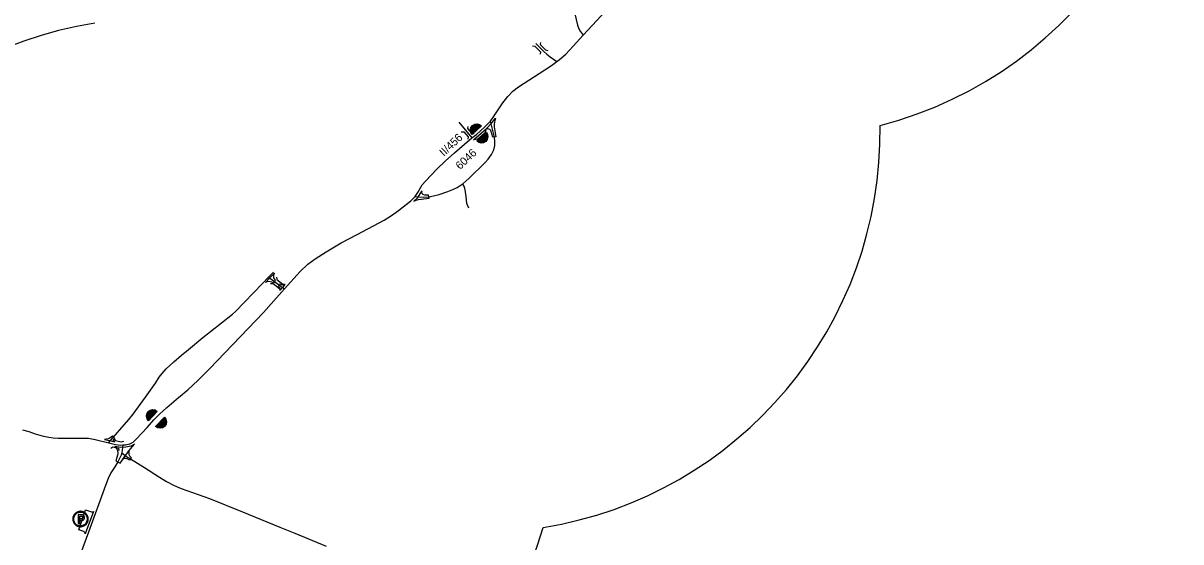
# Model space of a CAD drawing. Extents: x -546703 to -534152, y -1046534 to -1035676.
# Drawn here: x -543551 to -542104, y -1040697 to -1040049 of the extents above; entities that cross this region are included whole.
import ezdxf

# ---------------------------------------------------------------- set-up
doc = ezdxf.new("R2010")
doc.units = 0
for name, color, linetype in [('Vrstva 11', 7, 'Continuous'), ('Vrstva 19', 7, 'Continuous'), ('Vrstva 22', 7, 'Continuous'), ('Vrstva 23', 7, 'Continuous'), ('Vrstva 26', 7, 'Continuous'), ('Vrstva 3', 7, 'Continuous'), ('Vrstva 4', 7, 'Continuous'), ('Vrstva 46', 7, 'Continuous'), ('Vrstva 7', 7, 'Continuous'), ('Vrstva 8', 7, 'Continuous')]:
    doc.layers.add(name, color=color, linetype=linetype)

msp = doc.modelspace()

# ---------------------------------------------------------------- linework, layer by layer
at = {"layer": 'Vrstva 11'}
msp.add_line((-543006.5, -1040172.6), (-542990.1, -1040192.3), dxfattribs=at)
at = {"layer": 'Vrstva 19'}
msp.add_lwpolyline([(-543481.2, -1040681.7), (-543479.2, -1040675.6), (-543472.8, -1040656.7), (-543465.6, -1040659.1), (-543465.6, -1040659.1), (-543464.6, -1040659.2), (-543463.7, -1040659), (-543463, -1040658.6), (-543472, -1040683.4), (-543473.2, -1040686.6), (-543473.4, -1040685.2), (-543474, -1040684.4), (-543474.9, -1040683.8)], close=True, dxfattribs=at)
at = {"layer": 'Vrstva 22'}
msp.add_lwpolyline([(-543551.7, -1040556.7), (-543543.7, -1040559), (-543535.7, -1040561.7), (-543527.1, -1040564.4), (-543518.9, -1040566.1), (-543513.5, -1040566.6), (-543507, -1040567.2), (-543497.8, -1040567.2), (-543480.6, -1040567.3), (-543473.8, -1040567.3), (-543469.4, -1040567.4), (-543461, -1040568.9), (-543443.8, -1040573.1), (-543435.5, -1040574.9), (-543428.8, -1040575.8), (-543426.3, -1040575.7), (-543423.1, -1040575.5), (-543417.6, -1040574.1), (-543413.6, -1040572.1), (-543409.5, -1040568.4), (-543402.5, -1040560.9), (-543396, -1040553.7), (-543387.6, -1040544.5), (-543380.3, -1040537.1), (-543371.5, -1040528.8), (-543356.6, -1040516.5), (-543345.2, -1040507), (-543332.2, -1040494.9), (-543317.4, -1040480.4), (-543279.6, -1040440.7), (-543250.4, -1040410.4), (-543237.5, -1040395.7), (-543224.3, -1040380.6), (-543204.6, -1040359), (-543195.1, -1040350.1), (-543186.1, -1040343.3), (-543172.1, -1040334.6), (-543153.4, -1040323.5), (-543133.6, -1040312.8), (-543099.7, -1040295.1), (-543090.5, -1040289.3), (-543081.7, -1040282.9), (-543066.5, -1040270.7), (-543061, -1040265.5), (-543057.7, -1040260.7), (-543052.1, -1040251), (-543048.3, -1040246.3), (-543033.5, -1040231.1), (-543023.4, -1040221.3), (-543011.8, -1040210.8), (-542999.6, -1040200.1), (-542990.1, -1040192.3), (-542984.6, -1040187.9), (-542974.5, -1040179), (-542967, -1040171.3), (-542963, -1040166.1), (-542951.6, -1040148.7), (-542945.3, -1040140.6), (-542938.9, -1040133.9), (-542931.8, -1040128.4), (-542906.1, -1040112.1), (-542890.6, -1040101.9), (-542884.1, -1040096.9), (-542880.7, -1040094.4), (-542872.9, -1040087.6), (-542863.8, -1040077.9), (-542851, -1040064.2), (-542811.8, -1040021.9)], dxfattribs=at)
at = {"layer": 'Vrstva 23'}
for points in [[(-542989.4, -1040176.7), (-542986.7, -1040175.1), (-542983.6, -1040174.7), (-542980.5, -1040175.4), (-542978, -1040177.3), (-542990, -1040188.2), (-542991.7, -1040185.5), (-542992.1, -1040182.3), (-542991.3, -1040179.3)], [(-542989, -1040177.2), (-542986.5, -1040175.7), (-542983.6, -1040175.3), (-542980.8, -1040176), (-542979, -1040177.4), (-542989.9, -1040187.2), (-542991.1, -1040185.2), (-542991.5, -1040182.4), (-542990.8, -1040179.5)], [(-542988.6, -1040177.6), (-542986.3, -1040176.3), (-542983.7, -1040175.9), (-542981.1, -1040176.5), (-542979.9, -1040177.4), (-542989.8, -1040186.3), (-542990.5, -1040185), (-542990.9, -1040182.4), (-542990.2, -1040179.8)], [(-542988.2, -1040178.1), (-542986.1, -1040176.8), (-542983.7, -1040176.5), (-542981.3, -1040177.1), (-542980.8, -1040177.4), (-542989.6, -1040185.4), (-542989.9, -1040184.8), (-542990.3, -1040182.4), (-542989.7, -1040180)], [(-542987.8, -1040178.5), (-542985.9, -1040177.4), (-542983.7, -1040177.1), (-542981.9, -1040177.6), (-542989.4, -1040184.4), (-542989.7, -1040182.4), (-542989.1, -1040180.3)], [(-542987.4, -1040179), (-542985.7, -1040178), (-542983.8, -1040177.7), (-542983.1, -1040177.9), (-542989, -1040183.2), (-542989.1, -1040182.5), (-542988.6, -1040180.6)], [(-542987, -1040179.5), (-542985.5, -1040178.6), (-542984.6, -1040178.4), (-542988.2, -1040181.7), (-542988, -1040180.8)], [(-542972.8, -1040196.7), (-542975.5, -1040198.3), (-542978.6, -1040198.8), (-542981.7, -1040198), (-542984.2, -1040196.1), (-542972.1, -1040185.3), (-542970.5, -1040188), (-542970.1, -1040191.1), (-542970.9, -1040194.2)], [(-542973.2, -1040196.2), (-542975.7, -1040197.7), (-542978.6, -1040198.1), (-542981.4, -1040197.4), (-542983.2, -1040196), (-542972.3, -1040186.2), (-542971.1, -1040188.2), (-542970.7, -1040191.1), (-542971.4, -1040193.9)], [(-542973.6, -1040195.8), (-542975.9, -1040197.2), (-542978.5, -1040197.5), (-542981.1, -1040196.9), (-542982.3, -1040196), (-542972.4, -1040187.1), (-542971.7, -1040188.4), (-542971.3, -1040191.1), (-542972, -1040193.6)], [(-542974, -1040195.3), (-542976.1, -1040196.6), (-542978.5, -1040196.9), (-542980.9, -1040196.3), (-542981.4, -1040195.9), (-542972.5, -1040188.1), (-542972.2, -1040188.6), (-542971.9, -1040191), (-542972.5, -1040193.4)], [(-542974.4, -1040194.9), (-542976.3, -1040196), (-542978.5, -1040196.3), (-542980.3, -1040195.8), (-542972.8, -1040189.1), (-542972.5, -1040191), (-542973.1, -1040193.1)], [(-542974.8, -1040194.4), (-542976.5, -1040195.4), (-542978.4, -1040195.7), (-542979.1, -1040195.5), (-542973.2, -1040190.3), (-542973.1, -1040190.9), (-542973.6, -1040192.9)], [(-542975.2, -1040194), (-542976.7, -1040194.8), (-542977.6, -1040195), (-542973.9, -1040191.7), (-542974.2, -1040192.6)], [(-543394.7, -1040534.1), (-543392.1, -1040532.2), (-543389.1, -1040531.5), (-543385.9, -1040532), (-543383.2, -1040533.7), (-543394.2, -1040545.5), (-543396.1, -1040543), (-543396.8, -1040539.9), (-543396.3, -1040536.8)], [(-543394.2, -1040534.5), (-543391.9, -1040532.8), (-543389, -1040532.1), (-543386.1, -1040532.6), (-543384.2, -1040533.8), (-543394.2, -1040544.6), (-543395.5, -1040542.7), (-543396.2, -1040539.9), (-543395.8, -1040537)], [(-543393.8, -1040534.9), (-543391.6, -1040533.3), (-543389, -1040532.7), (-543386.4, -1040533.1), (-543385.1, -1040533.9), (-543394.1, -1040543.7), (-543395, -1040542.5), (-543395.6, -1040539.9), (-543395.2, -1040537.2)], [(-543393.3, -1040535.3), (-543391.4, -1040533.9), (-543389, -1040533.3), (-543386.6, -1040533.7), (-543386, -1040534), (-543394.1, -1040542.7), (-543394.4, -1040542.2), (-543395, -1040539.8), (-543394.6, -1040537.4)], [(-543392.9, -1040535.8), (-543391.1, -1040534.5), (-543389, -1040533.9), (-543387.1, -1040534.3), (-543393.9, -1040541.7), (-543394.4, -1040539.8), (-543394, -1040537.6)], [(-543392.4, -1040536.2), (-543390.8, -1040535), (-543388.9, -1040534.6), (-543388.3, -1040534.7), (-543393.6, -1040540.5), (-543393.8, -1040539.8), (-543393.5, -1040537.8)], [(-543392, -1040536.6), (-543390.6, -1040535.6), (-543389.7, -1040535.4), (-543393, -1040538.9), (-543392.9, -1040538.1)], [(-543373.9, -1040552.3), (-543376.5, -1040554.2), (-543379.6, -1040554.9), (-543382.7, -1040554.3), (-543385.3, -1040552.7), (-543374.2, -1040540.9), (-543372.4, -1040543.5), (-543371.7, -1040546.6), (-543372.2, -1040549.7)], [(-543374.3, -1040551.9), (-543376.7, -1040553.6), (-543379.6, -1040554.3), (-543382.4, -1040553.8), (-543384.4, -1040552.5), (-543374.3, -1040541.8), (-543372.9, -1040543.7), (-543372.3, -1040546.6), (-543372.8, -1040549.5)], [(-543374.8, -1040551.5), (-543377, -1040553.1), (-543379.6, -1040553.7), (-543382.2, -1040553.2), (-543383.5, -1040552.4), (-543374.3, -1040542.8), (-543373.5, -1040544), (-543372.9, -1040546.6), (-543373.4, -1040549.2)], [(-543375.2, -1040551.1), (-543377.2, -1040552.5), (-543379.6, -1040553), (-543382, -1040552.6), (-543382.5, -1040552.3), (-543374.4, -1040543.7), (-543374.1, -1040544.2), (-543373.5, -1040546.6), (-543373.9, -1040549)], [(-543375.7, -1040550.7), (-543377.5, -1040551.9), (-543379.6, -1040552.4), (-543381.5, -1040552.1), (-543374.5, -1040544.8), (-543374.1, -1040546.6), (-543374.5, -1040548.8)], [(-543376.1, -1040550.2), (-543377.7, -1040551.4), (-543379.6, -1040551.8), (-543380.3, -1040551.7), (-543374.9, -1040546), (-543374.7, -1040546.6), (-543375.1, -1040548.6)], [(-543376.6, -1040549.8), (-543378, -1040550.8), (-543378.8, -1040551), (-543375.5, -1040547.5), (-543375.6, -1040548.4)]]:
    msp.add_lwpolyline(points, close=True, dxfattribs=at)
at = {"layer": 'Vrstva 26'}
for centre, start, end in [((-542604.4, -1039692.4), 284.3744, 180.9424), ((-543382.4, -1040542.8), 99.089, 344.2283), ((-542980.2, -1040185), 279.089, 0.9424)]:
    msp.add_arc(centre, 500, start, end, dxfattribs=at)
at = {"layer": 'Vrstva 3'}
msp.add_lwpolyline([(-543551.7, -1040556.7), (-543543.7, -1040559), (-543535.7, -1040561.7), (-543527.1, -1040564.4), (-543518.9, -1040566.1), (-543513.5, -1040566.6), (-543507, -1040567.2), (-543497.8, -1040567.2), (-543480.6, -1040567.3), (-543473.8, -1040567.3), (-543469.4, -1040567.4), (-543461, -1040568.9), (-543443.8, -1040573.1), (-543435.5, -1040574.9), (-543428.8, -1040575.8), (-543426.3, -1040575.7), (-543423.1, -1040575.5), (-543417.6, -1040574.1), (-543413.6, -1040572.1), (-543409.5, -1040568.4), (-543402.5, -1040560.9), (-543396, -1040553.7), (-543387.6, -1040544.5), (-543380.3, -1040537.1), (-543371.5, -1040528.8), (-543356.6, -1040516.5), (-543345.2, -1040507), (-543332.2, -1040494.9), (-543317.4, -1040480.4), (-543279.6, -1040440.7), (-543250.4, -1040410.4), (-543237.5, -1040395.7), (-543224.3, -1040380.6), (-543204.6, -1040359), (-543195.1, -1040350.1), (-543186.1, -1040343.3), (-543172.1, -1040334.6), (-543153.4, -1040323.5), (-543133.6, -1040312.8), (-543099.7, -1040295.1), (-543090.5, -1040289.3), (-543081.7, -1040282.9), (-543066.5, -1040270.7), (-543061, -1040265.5), (-543057.7, -1040260.7), (-543052.1, -1040251), (-543048.3, -1040246.3), (-543033.5, -1040231.1), (-543023.4, -1040221.3), (-543011.8, -1040210.8), (-542999.6, -1040200.1), (-542990.1, -1040192.3), (-542984.6, -1040187.9), (-542974.5, -1040179), (-542967, -1040171.3), (-542963, -1040166.1), (-542951.6, -1040148.7), (-542945.3, -1040140.6), (-542938.9, -1040133.9), (-542931.8, -1040128.4), (-542906.1, -1040112.1), (-542890.6, -1040101.9), (-542884.1, -1040096.9), (-542880.7, -1040094.4), (-542872.9, -1040087.6), (-542863.8, -1040077.9), (-542851, -1040064.2), (-542811.8, -1040021.9)], dxfattribs=at)
msp.add_lwpolyline([(-542972.3, -1040181.1), (-542973.8, -1040186.4), (-542982.8, -1040194), (-542988.2, -1040194.6)], close=True, dxfattribs=at)
at = {"layer": 'Vrstva 4'}
msp.add_lwpolyline([(-543426.3, -1040575.7), (-543427.7, -1040585.7), (-543428.4, -1040588.5), (-543432.4, -1040596.9), (-543436.2, -1040602.8), (-543441.2, -1040610.5), (-543444.8, -1040617.5), (-543448.1, -1040626.1), (-543469.2, -1040684.5), (-543479.2, -1040711.6)], dxfattribs=at)
msp.add_lwpolyline([(-543429.7, -1040598.3), (-543420.6, -1040585.4), (-543416.8, -1040580.5), (-543411.9, -1040574.6), (-543416.5, -1040577), (-543422.7, -1040578.5), (-543428.9, -1040578.9), (-543436.2, -1040577.8), (-543433.6, -1040580.5), (-543432.8, -1040582.7), (-543432.6, -1040586.2), (-543432.8, -1040588.6), (-543433.6, -1040591.4), (-543435, -1040595.4)], close=True, dxfattribs=at)
at = {"layer": 'Vrstva 46'}
for points in [[(-543479.2, -1040658.5), (-543480, -1040658.5), (-543481.2, -1040658.7), (-543482.4, -1040659.1), (-543483.5, -1040659.5), (-543484.5, -1040660.1), (-543485.5, -1040660.9), (-543486.4, -1040661.7), (-543487.1, -1040662.7), (-543487.7, -1040663.7), (-543488.2, -1040664.8), (-543488.6, -1040666), (-543488.8, -1040667.2), (-543488.8, -1040668.4), (-543488.7, -1040669.6), (-543488.4, -1040670.8), (-543488, -1040672), (-543487.5, -1040673), (-543486.8, -1040674), (-543486, -1040674.9), (-543485.1, -1040675.7), (-543484, -1040676.4), (-543483, -1040677), (-543481.8, -1040677.4), (-543480.6, -1040677.6), (-543479.4, -1040677.7), (-543478.2, -1040677.7), (-543477, -1040677.5), (-543475.8, -1040677.1), (-543474.7, -1040676.6), (-543473.7, -1040676), (-543472.7, -1040675.2), (-543471.9, -1040674.4), (-543471.2, -1040673.4), (-543470.6, -1040672.3), (-543470.1, -1040671.2), (-543469.8, -1040670), (-543469.6, -1040668.8), (-543469.6, -1040667.6), (-543469.8, -1040666.4), (-543470, -1040665.2), (-543470.5, -1040664.1), (-543471.1, -1040663), (-543471.8, -1040662), (-543472.6, -1040661.2), (-543473.5, -1040660.4), (-543474.5, -1040659.7), (-543475.6, -1040659.2), (-543476.8, -1040658.8), (-543478, -1040658.6), (-543479.2, -1040658.5)], [(-543470.6, -1040668.1), (-543470.6, -1040667), (-543470.8, -1040666), (-543471.2, -1040664.9), (-543471.6, -1040663.9), (-543472.2, -1040663), (-543472.9, -1040662.2), (-543473.7, -1040661.4), (-543474.6, -1040660.8), (-543475.6, -1040660.3), (-543476.6, -1040659.9), (-543477.7, -1040659.6), (-543478.7, -1040659.5), (-543479.8, -1040659.5), (-543480.9, -1040659.6), (-543482, -1040659.9), (-543483, -1040660.3), (-543483.9, -1040660.9), (-543484.8, -1040661.5), (-543485.6, -1040662.3), (-543486.3, -1040663.2), (-543486.9, -1040664.1), (-543487.3, -1040665.1), (-543487.6, -1040666.1), (-543487.8, -1040667.2), (-543487.8, -1040668.3), (-543487.8, -1040669.4), (-543487.5, -1040670.5), (-543487.2, -1040671.5), (-543486.7, -1040672.5), (-543486.1, -1040673.4), (-543485.3, -1040674.2), (-543484.5, -1040674.9), (-543483.6, -1040675.5), (-543482.7, -1040676), (-543481.6, -1040676.4), (-543480.6, -1040676.7), (-543479.5, -1040676.8), (-543478.4, -1040676.7), (-543477.3, -1040676.6), (-543476.3, -1040676.2), (-543475.3, -1040675.8), (-543474.3, -1040675.3), (-543473.5, -1040674.6), (-543472.7, -1040673.8), (-543472, -1040672.9), (-543471.5, -1040672), (-543471, -1040671), (-543470.7, -1040669.9), (-543470.6, -1040668.8), (-543470.6, -1040668.1)], [(-543479.2, -1040659.5), (-543478.5, -1040659.5), (-543477.4, -1040659.7), (-543476.3, -1040660), (-543475.3, -1040660.4), (-543474.4, -1040660.9), (-543473.5, -1040661.6), (-543472.8, -1040662.4), (-543472.1, -1040663.2), (-543471.5, -1040664.2), (-543471.1, -1040665.2), (-543470.8, -1040666.2), (-543470.6, -1040667.3), (-543470.6, -1040668.4), (-543470.7, -1040669.5), (-543470.9, -1040670.5), (-543471.3, -1040671.6), (-543471.8, -1040672.5), (-543472.4, -1040673.4), (-543473.1, -1040674.3), (-543473.9, -1040675), (-543474.9, -1040675.6), (-543475.8, -1040676.1), (-543476.9, -1040676.4), (-543477.9, -1040676.7), (-543479, -1040676.8), (-543480.1, -1040676.7), (-543481.2, -1040676.5), (-543482.2, -1040676.2), (-543483.2, -1040675.8), (-543484.2, -1040675.2), (-543485, -1040674.5), (-543485.8, -1040673.7), (-543486.4, -1040672.9), (-543487, -1040671.9), (-543487.4, -1040670.9), (-543487.7, -1040669.8), (-543487.8, -1040668.8), (-543487.8, -1040667.7), (-543487.7, -1040666.6), (-543487.5, -1040665.5), (-543487.1, -1040664.5), (-543486.5, -1040663.5), (-543485.9, -1040662.7), (-543485.2, -1040661.9), (-543484.3, -1040661.1), (-543483.4, -1040660.6), (-543482.4, -1040660.1), (-543481.4, -1040659.8), (-543480.3, -1040659.5), (-543479.2, -1040659.5)], [(-543477.6, -1040662.9), (-543482.3, -1040662.9), (-543482.3, -1040673.8), (-543480, -1040673.8), (-543480, -1040668.1)], [(-543480, -1040668.1), (-543480, -1040664.7)], [(-543480, -1040664.7), (-543478.1, -1040664.7)], [(-543478.1, -1040668.1), (-543480, -1040668.1)], [(-543480, -1040668.1), (-543480, -1040669.9)], [(-543480, -1040669.9), (-543477.6, -1040669.9)], [(-543479.2, -1040658.5), (-543479.2, -1040659.5)], [(-543479.2, -1040659.5), (-543479.2, -1040658.5)], [(-543478.1, -1040664.7), (-543478.1, -1040664.7), (-543478, -1040664.7), (-543477.5, -1040664.8), (-543477.4, -1040664.9), (-543477.2, -1040665), (-543477, -1040665.1), (-543476.9, -1040665.2), (-543476.7, -1040665.4), (-543476.5, -1040665.7), (-543476.4, -1040665.9), (-543476.3, -1040666.3), (-543476.3, -1040666.5), (-543476.4, -1040666.9), (-543476.5, -1040667.1), (-543476.7, -1040667.4), (-543476.8, -1040667.5), (-543476.9, -1040667.6), (-543477.2, -1040667.8), (-543477.4, -1040667.9), (-543477.6, -1040668), (-543478, -1040668.1), (-543478.1, -1040668.1)], [(-543477.6, -1040669.9), (-543477.1, -1040669.8), (-543476.8, -1040669.8), (-543476.5, -1040669.7), (-543476.3, -1040669.6), (-543476.1, -1040669.5), (-543475.9, -1040669.4), (-543475.7, -1040669.2), (-543475.4, -1040669.1), (-543475.2, -1040668.9), (-543475.1, -1040668.7), (-543474.9, -1040668.6), (-543474.7, -1040668.3), (-543474.6, -1040668.1), (-543474.5, -1040667.9), (-543474.4, -1040667.7), (-543474.3, -1040667.5), (-543474.2, -1040667.2), (-543474.1, -1040666.8), (-543474.1, -1040666.5), (-543474.1, -1040666.2), (-543474.2, -1040665.8), (-543474.2, -1040665.7), (-543474.3, -1040665.4), (-543474.4, -1040665.2), (-543474.6, -1040664.8), (-543474.7, -1040664.6), (-543474.9, -1040664.3), (-543475.1, -1040664.1), (-543475.2, -1040664), (-543475.4, -1040663.8), (-543475.7, -1040663.6), (-543475.9, -1040663.5), (-543476.1, -1040663.4), (-543476.3, -1040663.3), (-543476.5, -1040663.2), (-543476.7, -1040663.1), (-543477.1, -1040663), (-543477.6, -1040662.9)]]:
    msp.add_lwpolyline(points, dxfattribs=at)
at = {"layer": 'Vrstva 7'}
msp.add_line((-543244.2, -1040366.4), (-543224.3, -1040380.6), dxfattribs=at)
for points in [[(-542877.6, -1040030.5), (-542869.3, -1040028.9), (-542867.2, -1040029), (-542864.5, -1040030.1), (-542863, -1040032), (-542858.3, -1040051.6), (-542856.7, -1040056), (-542855.1, -1040059), (-542851, -1040064.2)], [(-542910.4, -1040074.4), (-542900.3, -1040084.4), (-542896.6, -1040088), (-542892.2, -1040091.1), (-542884.1, -1040096.9)], [(-543061, -1040265.5), (-543050.5, -1040266.5), (-543044, -1040265.8), (-543038.3, -1040264.6), (-543031.2, -1040262.8), (-543020.2, -1040259.1), (-543013.8, -1040256.8), (-543008.4, -1040254.3), (-543001.1, -1040249.4), (-542994.1, -1040243.2), (-542973.4, -1040223.2), (-542969.8, -1040218.8), (-542965.5, -1040213), (-542962.6, -1040207.4), (-542961.6, -1040201.9), (-542961.5, -1040196.7), (-542962.1, -1040191.3), (-542967, -1040171.3)], [(-542994.1, -1040280), (-542996.3, -1040274.3), (-542997.4, -1040265.5), (-542998.6, -1040257.2), (-542999.6, -1040253.4), (-543001.6, -1040249.9)], [(-543444.4, -1040572.9), (-543418.8, -1040544.1), (-543413.3, -1040537.3), (-543398.1, -1040516.2), (-543385.4, -1040498.4), (-543381, -1040491.1), (-543377.1, -1040486.4), (-543372, -1040480.8), (-543362.4, -1040471.7), (-543353.1, -1040463.4), (-543344.1, -1040456.4), (-543326.3, -1040441.6), (-543316.8, -1040433.9), (-543289.4, -1040412.4), (-543285.4, -1040408.9), (-543251.6, -1040374), (-543244.2, -1040366.4), (-543241.8, -1040363.8), (-543238.1, -1040359.8)], [(-543427.7, -1040585.7), (-543421.8, -1040590.1), (-543416.9, -1040593.1), (-543399.1, -1040603.9), (-543380.4, -1040615.8), (-543371.8, -1040621.2), (-543362.3, -1040626.2), (-543353.4, -1040629.9), (-543317.9, -1040642.5), (-543276.9, -1040659.1), (-543230.2, -1040678.3), (-543211.3, -1040685.9), (-543172.1, -1040702.1)]]:
    msp.add_lwpolyline(points, dxfattribs=at)
for points in [[(-542964.1, -1040191.6), (-542966.6, -1040183.3), (-542967.9, -1040181.7), (-542970.1, -1040180.9), (-542972.3, -1040181.1), (-542964.7, -1040173.2), (-542960.5, -1040167.8), (-542961.9, -1040172.8), (-542962.2, -1040175.3), (-542962.4, -1040178.7), (-542960.1, -1040190.9)], [(-543044.3, -1040263.8), (-543048.8, -1040263.7), (-543051.2, -1040262.8), (-543052.1, -1040261.9), (-543052.9, -1040260.2), (-543052.9, -1040258.4), (-543055.1, -1040262.3), (-543058.7, -1040267.5), (-543062.9, -1040271.4), (-543059.9, -1040270), (-543056.7, -1040269.2), (-543053.1, -1040268.8), (-543050.4, -1040268.5), (-543043.7, -1040267.7)], [(-543236.8, -1040361), (-543238, -1040363.5), (-543238.2, -1040365.4), (-543238, -1040366.9), (-543237.1, -1040368.4), (-543235.9, -1040369.9), (-543238, -1040373.3), (-543240, -1040372.4), (-543242.2, -1040371.9), (-543244.7, -1040371.8), (-543246.2, -1040372.2), (-543248.2, -1040373), (-543243, -1040367.6)], [(-543223.7, -1040375.5), (-543226.5, -1040378.6), (-543229.9, -1040382.6), (-543229.7, -1040381.7), (-543229.8, -1040380.1), (-543230.4, -1040379), (-543231.9, -1040377.7), (-543229.3, -1040374.6), (-543228, -1040375.3), (-543226.4, -1040375.8), (-543225.1, -1040375.9)], [(-543436.5, -1040571.6), (-543437.8, -1040570.6), (-543438.1, -1040569.6), (-543437.7, -1040568.3), (-543436.6, -1040566.8), (-543439.4, -1040564.6), (-543441, -1040566), (-543442.5, -1040567.2), (-543444.5, -1040568), (-543446.7, -1040568.5), (-543449.3, -1040568.7), (-543443.1, -1040570.1)], [(-543420.6, -1040585.4), (-543418.6, -1040582.9), (-543419, -1040585.3), (-543418.7, -1040587.5), (-543418, -1040589.2), (-543416.5, -1040591.1), (-543416, -1040591.6), (-543417.8, -1040594.6), (-543420.7, -1040593.2), (-543422.7, -1040592.6), (-543424.2, -1040592.6), (-543426.3, -1040593.6)]]:
    msp.add_lwpolyline(points, close=True, dxfattribs=at)
at = {"layer": 'Vrstva 8'}
for points in [[(-542914.3, -1040077.6), (-542911.4, -1040078), (-542904.4, -1040084.8), (-542904.7, -1040087.6)], [(-542904.4, -1040073.1), (-542904.7, -1040075.6), (-542898.1, -1040082.4), (-542895.2, -1040083.2)], [(-542995.3, -1040177.9), (-542995.5, -1040180.8), (-542990.2, -1040186.7), (-542987.4, -1040186.7)], [(-543003.6, -1040184.9), (-543000.2, -1040184.9), (-542994.7, -1040190.9), (-542995.1, -1040193.9)], [(-543234.5, -1040366.2), (-543233.9, -1040369.3), (-543226.2, -1040375), (-543223.5, -1040374.9)], [(-543241.7, -1040374.1), (-543238.4, -1040374.1), (-543230.4, -1040380.4), (-543230, -1040382.9)], [(-543436.9, -1040567.6), (-543436, -1040570.3), (-543427.8, -1040571.8), (-543425, -1040570.9)], [(-543441.2, -1040579.7), (-543438.6, -1040578.2), (-543431.8, -1040579.8), (-543431.1, -1040582.5)]]:
    msp.add_lwpolyline(points, dxfattribs=at)

# ---------------------------------------------------------------- texts
at = {"layer": 'Vrstva 22'}
msp.add_text('6046', height=10, rotation=43.4649, dxfattribs=at).set_placement((-543004.9, -1040232.6))
at = {"layer": 'Vrstva 3'}
msp.add_text('II/456', height=10, rotation=43.4649, dxfattribs=at).set_placement((-543025.2, -1040216))

doc.saveas('drawing.dxf')
